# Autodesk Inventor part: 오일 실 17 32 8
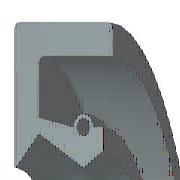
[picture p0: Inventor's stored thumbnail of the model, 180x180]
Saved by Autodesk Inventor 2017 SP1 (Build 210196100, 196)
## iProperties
IsCustomPart: 0
Created: 2018-09
Part Number: 오일 실 17 32 8
Material: 고무
Description: 오일-실
Document SubType Name: Modeling
Standard: KS B 2804
Standards Organization: KS
Language: ko-KR
Size Designation: D - 17 32 8
Categories: <MemberInstance><Categories><Category DisplayName="샤프트 부품" InternalName="7f7aeb1f-a693-4053-b835-cee3144e0d98" Mnemonic="SHFT"><Category DisplayName="실링" Intern
Density: 0.93 g/cm^3
Appearance: 고무 - 검은색 - 버전 1.1
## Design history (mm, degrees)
revolve "본체" stored, may be unused: angle "d17" = 90 deg
revolve "스프링1" stored, may be unused: angle "d18" = 90 deg
body "Solid1"
sketch "스케치1"
  geometry: L1 (0, 16)-(8, 16); L2 (8, 14.25)-(1.75, 14.25); L3 (1.75, 10.25)-(4.9, 8.5); L4 (4.9, 8.5)-(0, 8.5); L5 (0, 0)-(9.586, 0) reference; L6 (4.9, 8.5)-(6.3, 9.375); L7 (0, 18)-(0, -3) reference; L8 (-1.941, 0)-(11.507, 0) reference; L9 (4.2, 10.6)-(1.75, 11.21); L10 (1.75, 11.21)-(1.75, 14.25); L11 (0, 16)-(0, 8.588); L12 (4.9, 8.5)-(0, 8.5); L13 (1.75, 10.25)-(0.152, 8.528); L14 (8, 16)-(8, 14.25); L15 (5.6, 10.6)-(6.3, 10.6); L16 (6.3, 10.6)-(6.3, 9.375); C1 r 0.455 at (4.9, 10.6); A1 r 0.7 centre (4.9, 10.6) between (5.6, 10.6) and (4.2, 10.6); A2 r 0.088 centre (0.088, 8.588) between (0, 8.588) and (0.152, 8.528); 1 further point
  constraints: 28 end point, 5 horizontal alignment, 5 point on line, 4 point on circle, 4 vertical alignment, 3 centre point, 3 tangent, 2 collinear, 2 horizontal, 2 perpendicular, 1 coincident, 1 parallel
  dimensions: "d0" = 32 diameter of L1 L5 (= SD2); "d1" = 1.75 distance of L1.end L2.start (= SD); "d2" = 0.91 diameter of C1 (= SPDI); "d3" = 1.4 diameter of A1 (= SPDA); "d4" = 17 diameter of L3.end L5 (= NND); "d5" = 20.5 diameter of L3.start L5 (= TKDM); "d7" = 22.42 diameter of L9.end L5 (= TKDM + 0.24 x SWDT); "d8" = 1.75 distance between parallel lines of L11 L10 (= SD); "d9" = 4.9 distance from line of L11 C1.centre (= SPDST); "d10" = 21.2 diameter of C1.centre L5 (= HLDM); "d11" = 0.0875 radius of A2 (= 0.25 x LAB); "d12" = 6.3 distance between parallel lines of L11 L16 (= SDI); "d13" = 18.75 diameter of L6.end L5 (= ABDM); "d14" = 8 distance from line of L11 L1.end (= SWDT)
fillet "모깎기1" dims "d6" = 0.3 (= RR)
other parameters: "SD2" = 32 [user parameter; used in 1 equation term], "SWDT" = 8 [user parameter; used in 2 equation terms], "RR" = 0.3 [user parameter; used in 1 equation term], "SD" = 1.75 [user parameter; used in 2 equation terms], "NND" = 17 [user parameter; used in 1 equation term], "SPDA" = 1.4 [user parameter; used in 1 equation term], "SPDI" = 0.91 [user parameter; used in 1 equation term], "TKDM" = 20.5 [user parameter; used in 2 equation terms], "HLDM" = 21.2 [user parameter; used in 1 equation term], "ABDM" = 18.75 [user parameter; used in 1 equation term], "SDI" = 6.3 [user parameter; used in 1 equation term], "SPDST" = 4.9 [user parameter; used in 1 equation term], "LAB" = 0.35 [user parameter; used in 1 equation term], "d15" = 0, "d16" = 0, "d19" = 0
